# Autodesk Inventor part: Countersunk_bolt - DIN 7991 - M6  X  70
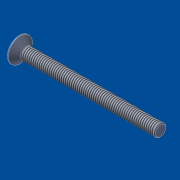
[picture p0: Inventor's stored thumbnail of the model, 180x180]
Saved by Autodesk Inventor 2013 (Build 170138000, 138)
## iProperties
Shininess: 20.0
Length Units: 11269
Angle Units: 11279
Time Units: 11290
Mass Units: 11283
Length Display Precision: 3
Angle Display Precision: 2
Created: 2001-04
Part Number: Countersunk_bolt - DIN 7991 - M6  X  70
Material: Standard
Document SubType Name: Modellieren
Designer: dl
Density: 1 g/cm^3
Density: 0.0
Volumn: 0.0
Area: 0.0
PropertySet Name: Model Information
Control State: 0
Master: False
Checked Out: False
Author: dl
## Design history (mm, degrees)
body "Solid1"
sketch "Sketch2"
  geometry: L1 (-1.129, 2.044)-(1.129, 2.044); L2 (1.129, 2.044)-(2.309, 0); L3 (2.309, 0)-(1.18, -1.956); L4 (1.18, -1.956)-(-1.18, -1.956); L5 (-1.18, -1.956)-(-2.309, 0); L6 (-2.309, 0)-(-1.129, 2.044); C1 r 6 at (0, 0) reference
  constraints: 12 end point, 2 parallel, 1 horizontal
  dimensions: "d6" = 4 distance between parallel lines of L4 L1; "d7" = 4 distance between parallel lines of L3 L6 (= d6); "d8" = 4 distance between parallel lines of L5 L2 (= d6); "d9" = 120 deg angle of L5 L6; "d10" = 120 deg angle of L6 L1 (= d9); "d11" = 0 vertical distance of L5.end C1.centre; "d12" = 2 distance from line of C1.centre L6 (= 0.5 x d6)
extrude "Extrusion1" cut sketch "Sketch2" distance "d13" = 3; taper "d14" = 0 deg
sketch "Sketch3"
  geometry: C1 r 6 at (0, 0) reference; 1 further point
  constraints: 1 coincident
revolve "Revolution1" stored, may be unused: angle "d5" = 90 deg
hole "Hole1" sketch "Sketch3" diameter "d15" = 4; stored, may be unused: countersink angle "d19" = 60 deg, drill point angle "d21" = 118 deg; dims "d16" = 6, "d17" = 4, "d18" = 2, "d20" = 3
thread "Thread1" dims "d22" = 10, "d23" = 0
chamfer "Chamfer1" distance "d24" = 0.5; stored, may be unused: second distance "d25" = 0.5, angle "d26" = 45 deg
sketch "Sketch1"
  geometry: L1 (0.168, 2.141)-(0.168, 8.141); L2 (0.168, 8.141)-(0.668, 8.141); L3 (0.668, 8.141)-(3.668, 5.141); L4 (3.668, 5.141)-(70.168, 5.141); L5 (70.168, 5.141)-(70.168, 2.141); L6 (70.168, 2.141)-(0.168, 2.141)
  constraints: 12 end point, 3 parallel, 1 perpendicular, 1 vertical
  dimensions: "d0" = 6 distance of L1.start L1.end; "d1" = 0.5 distance of L1.end L2.end; "d2" = 45 deg angle of L3 L4; "d3" = 3 distance of L4.end L5.end; "d4" = 70 distance of L5.end L1.start
